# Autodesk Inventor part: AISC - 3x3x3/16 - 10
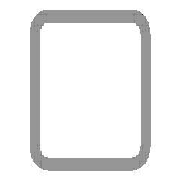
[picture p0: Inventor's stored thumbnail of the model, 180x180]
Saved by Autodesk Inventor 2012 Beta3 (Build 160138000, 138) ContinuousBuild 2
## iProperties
IsCustomPart: 1
Created: 2011-01
Part Number: AISC - 3x3x3/16 - 10
Material: Steel, Mild
Description: Tube
Document SubType Name: Modeling
Standard: ANSI
Designer: Beta-8540w
Standards Organization: ANSI
Language: en-US
Size Designation: 3x3x3/16
Categories: <MemberInstance><Categories><Category DisplayName="Structural Shapes" InternalName="089c4875-fa83-4c05-b084-43b9cc11f5ed" Mnemonic="GRDR"><CategoryParameter Dis
Stock Number: 3x3x3/16
Density: 7.86 g/cm^3
_CCFamilyMember: 9
_CCFamilyDisplayName: ANSI AISC (Square) - Tube
_FrameMemberDoc: Frame Member File
_Version: 15.0.0
_GetPNFromCC: 1
G_L: 10.000 in
G_W: 3.000 in
G_H: 3.000 in
Author: Beta-8540w
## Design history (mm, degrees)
node "Start plane"
node "End plane"
sketch "Sketch"
  geometry: L1 (-38.1, -28.575)-(-38.1, 28.575); L2 (-28.575, 38.1)-(28.575, 38.1); L3 (38.1, 28.575)-(38.1, -28.575); L4 (28.575, -38.1)-(-28.575, -38.1); L5 (-28.575, 33.337)-(28.575, 33.338); L6 (33.338, 28.575)-(33.338, -28.575); L7 (28.575, -33.337)-(-28.575, -33.338); L8 (-33.338, -28.575)-(-33.338, 28.575); L9 (0, 56.102)-(0, -56.102) reference; L10 (-56.102, 0)-(56.102, 0) reference; A1 r 9.525 centre (-28.575, -28.575) between (-38.1, -28.575) and (-28.575, -38.1); A2 r 9.525 centre (-28.575, 28.575) between (-28.575, 38.1) and (-38.1, 28.575); A3 r 9.525 centre (28.575, 28.575) between (38.1, 28.575) and (28.575, 38.1); A4 r 9.525 centre (28.575, -28.575) between (28.575, -38.1) and (38.1, -28.575); A5 r 4.763 centre (-28.575, 28.575) between (-28.575, 33.337) and (-33.338, 28.575); A6 r 4.763 centre (28.575, 28.575) between (33.338, 28.575) and (28.575, 33.338); A7 r 4.763 centre (28.575, -28.575) between (28.575, -33.337) and (33.338, -28.575); A8 r 4.763 centre (-28.575, -28.575) between (-33.338, -28.575) and (-28.575, -33.338)
  constraints: 16 end point, 16 point on circle, 8 centre point, 8 tangent, 4 parallel, 3 equal radius, 2 perpendicular, 7 other
  dimensions: "d10" = 76.2 distance between parallel lines of L2 L4 (= G_H); "d11" = 76.2 distance between parallel lines of L1 L3 (= G_W); "d12" = 4.7625 distance between parallel lines of L3 L6 (= G_T); "d15" = 38.1 distance between parallel lines of L2 L10 (= 0.5 x d10); "d16" = 38.1 distance between parallel lines of L9 L3 (= 0.5 x d11); "d17" = 9.525 radius of A1 (= G_IR)
extrude "Body" new body sketch "Sketch" stored distance "d3" = 254 (= G_L); taper "d4" = 0 deg
node "Driven Length"
  sketch "Sketch3"
    geometry: L1 (0, 0)-(10, 0) reference
    constraints: 2 end point, 1 horizontal
  workplane "Work Plane3"
  sketch "Sketch4"
    geometry: L1 (-2, 0)-(12, 0) reference; L2 (-2, 254)-(12, 254) reference
    dimensions: "d19" = 254 distance between parallel lines of L1 L2 (derived)
body "Solid1"
other parameters: "G_W" = 76.2 [user parameter; used in 1 equation term], "G_H" = 76.2 [user parameter; used in 1 equation term], "G_T" = 4.7625 [user parameter; used in 1 equation term], "G_IR" = 9.525 [user parameter; used in 1 equation term], "G_L" = 254 (= d19) [user parameter; used in 1 equation term], "G_OFFSET_START" = 0 [user parameter; used in 1 equation term], "G_OFFSET_END" = 0 [user parameter; used in 1 equation term], "d13" = 0 (computed from G_OFFSET_START), "d14" = 254 (= G_OFFSET_END + B_L), "B_L" = 254 [user parameter; used in 1 equation term], "d18" = 90 deg
